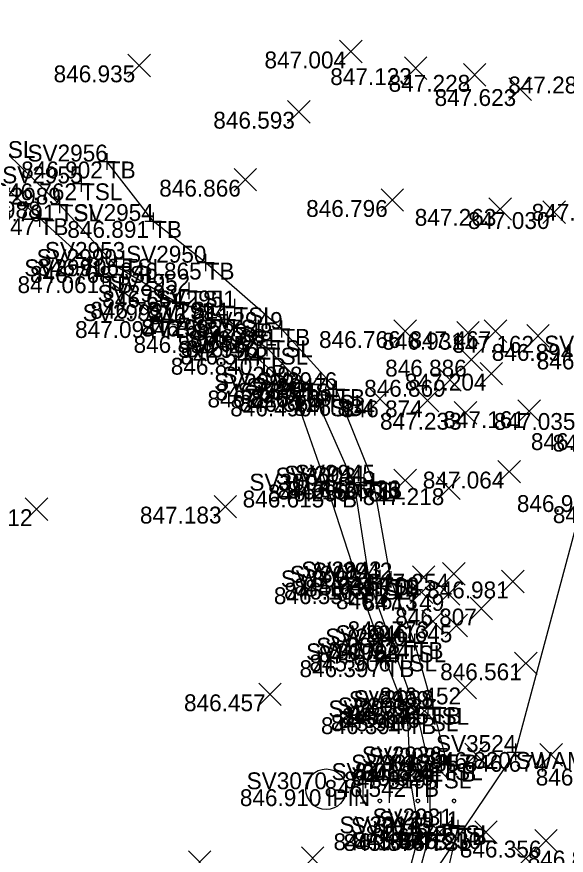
# Model space of a CAD drawing. Extents: x 2228183 to 2230895, y 679226 to 682223.
# Drawn here: x 2228252.61 to 2228285.17, y 680625.35 to 680675.06 of the extents above; entities that cross this region are included whole.
import ezdxf

# ---------------------------------------------------------------- set-up
doc = ezdxf.new("R2010")
doc.units = 0
for name, color, linetype in [('HY_X_Water_Edge', 7, 'Continuous'), ('RS_Raster1', 7, 'Continuous'), ('SC_Scratch1', 7, 'Continuous'), ('SV_P_Control_Cells_Set', 7, 'Continuous'), ('SV_X_Random_Point', 7, 'Continuous'), ('SV_X_Shot_Marker', 7, 'Continuous'), ('SV_X_Text_Comment', 7, 'Continuous'), ('SV_X_Toe_of_Slope', 7, 'Continuous'), ('SV_X_Top_of_Bank', 7, 'Continuous')]:
    doc.layers.add(name, color=color, linetype=linetype)

msp = doc.modelspace()

# ---------------------------------------------------------------- linework, layer by layer
at = {"layer": 'HY_X_Water_Edge'}
msp.add_lwpolyline([(2228257.254, 680599.372), (2228272.802, 680617.571), (2228282.168, 680631.469), (2228288.524, 680655.152), (2228295.689, 680691.668), (2228303.446, 680727.882), (2228301.785, 680777.477), (2228295.766, 680798.984)], dxfattribs=at)
at = {"layer": 'RS_Raster1'}
for points in [[(2228272.957, 680630.062), (2228273.31, 680630.062)], [(2228273.134, 680628.462), (2228273.134, 680630.062)], [(2228274.699, 680628.462), (2228274.699, 680630.062), (2228275.228, 680630.062), (2228275.283, 680630.049), (2228275.36, 680630.024), (2228275.394, 680629.999), (2228275.427, 680629.974), (2228275.471, 680629.911), (2228275.504, 680629.848), (2228275.526, 680629.747), (2228275.526, 680629.596), (2228275.515, 680629.545), (2228275.493, 680629.47), (2228275.449, 680629.382), (2228275.404, 680629.344), (2228275.371, 680629.319), (2228275.316, 680629.293), (2228275.228, 680629.281), (2228274.699, 680629.281)], [(2228277.708, 680630.062), (2228276.948, 680630.062), (2228276.948, 680628.462)], [(2228276.948, 680629.281), (2228277.488, 680629.281)], [(2228274.093, 680628.676), (2228274.148, 680628.676), (2228274.181, 680628.651), (2228274.214, 680628.601), (2228274.214, 680628.538), (2228274.181, 680628.487), (2228274.148, 680628.462), (2228274.093, 680628.462), (2228274.06, 680628.487), (2228274.027, 680628.538), (2228274.027, 680628.601), (2228274.06, 680628.651), (2228274.093, 680628.676)], [(2228276.342, 680628.676), (2228276.397, 680628.676), (2228276.43, 680628.651), (2228276.463, 680628.601), (2228276.463, 680628.538), (2228276.43, 680628.487), (2228276.397, 680628.462), (2228276.342, 680628.462), (2228276.308, 680628.487), (2228276.275, 680628.538), (2228276.275, 680628.601), (2228276.308, 680628.651), (2228276.342, 680628.676)], [(2228278.491, 680628.676), (2228278.546, 680628.676), (2228278.579, 680628.651), (2228278.612, 680628.601), (2228278.612, 680628.538), (2228278.579, 680628.487), (2228278.546, 680628.462), (2228278.491, 680628.462), (2228278.458, 680628.487), (2228278.425, 680628.538), (2228278.425, 680628.601), (2228278.458, 680628.651), (2228278.491, 680628.676)], [(2228272.957, 680628.462), (2228273.31, 680628.462)]]:
    msp.add_lwpolyline(points, dxfattribs=at)
msp.add_circle((2228270.943, 680629.262), 1.2, dxfattribs=at)
at = {"layer": 'SV_X_Random_Point'}
for p, q in [((2228271.742, 680672.332), (2228273.076, 680673.667)), ((2228271.742, 680673.667), (2228273.076, 680672.332)), ((2228259.198, 680671.507), (2228260.532, 680672.842)), ((2228259.198, 680672.842), (2228260.532, 680671.507)), ((2228275.583, 680671.343), (2228276.917, 680672.678)), ((2228275.583, 680672.678), (2228276.917, 680671.343)), ((2228279.077, 680670.946), (2228280.411, 680672.281)), ((2228279.077, 680672.281), (2228280.411, 680670.946)), ((2228281.765, 680670.103), (2228283.099, 680671.438)), ((2228281.765, 680671.438), (2228283.099, 680670.103)), ((2228268.653, 680668.759), (2228269.987, 680670.094)), ((2228268.653, 680670.094), (2228269.987, 680668.759)), ((2228265.49, 680664.729), (2228266.824, 680666.064)), ((2228265.49, 680666.064), (2228266.824, 680664.729)), ((2228274.194, 680663.525), (2228275.528, 680664.86)), ((2228274.194, 680664.86), (2228275.528, 680663.525)), ((2228280.588, 680662.998), (2228281.922, 680664.333)), ((2228280.588, 680664.333), (2228281.922, 680662.998)), ((2228283.788, 680662.81), (2228285.122, 680664.145)), ((2228283.788, 680664.145), (2228285.122, 680662.81)), ((2228274.958, 680655.756), (2228276.292, 680657.091)), ((2228274.958, 680657.091), (2228276.292, 680655.756)), ((2228280.313, 680655.747), (2228281.647, 680657.082)), ((2228280.313, 680657.082), (2228281.647, 680655.747)), ((2228278.679, 680655.654), (2228280.013, 680656.989)), ((2228278.679, 680656.989), (2228280.013, 680655.654)), ((2228282.829, 680655.472), (2228284.163, 680656.807)), ((2228282.829, 680656.807), (2228284.163, 680655.472)), ((2228278.875, 680654.059), (2228280.209, 680655.394)), ((2228278.875, 680655.394), (2228280.209, 680654.059)), ((2228280.059, 680653.231), (2228281.393, 680654.566)), ((2228280.059, 680654.566), (2228281.393, 680653.231)), ((2228277.61, 680652.867), (2228278.944, 680654.202)), ((2228277.61, 680654.202), (2228278.944, 680652.867)), ((2228273.463, 680651.736), (2228274.797, 680653.071)), ((2228273.463, 680653.071), (2228274.797, 680651.736)), ((2228276.284, 680651.646), (2228277.618, 680652.981)), ((2228276.284, 680652.981), (2228277.618, 680651.646)), ((2228278.532, 680650.913), (2228279.866, 680652.248)), ((2228278.532, 680652.248), (2228279.866, 680650.913)), ((2228282.298, 680651.009), (2228283.632, 680652.344)), ((2228282.298, 680652.344), (2228283.632, 680651.009)), ((2228281.121, 680647.425), (2228282.455, 680648.76)), ((2228281.121, 680648.76), (2228282.455, 680647.425)), ((2228274.957, 680646.904), (2228276.291, 680648.239)), ((2228274.957, 680648.239), (2228276.291, 680646.904)), ((2228277.542, 680646.444), (2228278.876, 680647.779)), ((2228277.542, 680647.779), (2228278.876, 680646.444)), ((2228264.306, 680645.347), (2228265.64, 680646.682)), ((2228264.306, 680646.682), (2228265.64, 680645.347)), ((2228253.114, 680645.195), (2228254.448, 680646.53)), ((2228253.114, 680646.53), (2228254.448, 680645.195)), ((2228277.839, 680641.366), (2228279.173, 680642.701)), ((2228277.839, 680642.701), (2228279.173, 680641.366)), ((2228276.049, 680641.163), (2228277.383, 680642.498)), ((2228276.049, 680642.498), (2228277.383, 680641.163)), ((2228281.34, 680640.911), (2228282.674, 680642.246)), ((2228281.34, 680642.246), (2228282.674, 680640.911)), ((2228275.925, 680640.267), (2228277.259, 680641.602)), ((2228275.925, 680641.602), (2228277.259, 680640.267)), ((2228277.523, 680640.173), (2228278.857, 680641.508)), ((2228277.523, 680641.508), (2228278.857, 680640.173)), ((2228279.465, 680639.305), (2228280.799, 680640.64)), ((2228279.465, 680640.64), (2228280.799, 680639.305)), ((2228276.609, 680638.549), (2228277.943, 680639.884)), ((2228276.609, 680639.884), (2228277.943, 680638.549)), ((2228277.985, 680638.305), (2228279.319, 680639.64)), ((2228277.985, 680639.64), (2228279.319, 680638.305)), ((2228282.111, 680636.056), (2228283.445, 680637.391)), ((2228282.111, 680637.391), (2228283.445, 680636.056)), ((2228278.507, 680634.626), (2228279.841, 680635.961)), ((2228278.507, 680635.961), (2228279.841, 680634.626)), ((2228266.95, 680634.221), (2228268.284, 680635.556)), ((2228266.95, 680635.556), (2228268.284, 680634.221)), ((2228276.099, 680633.231), (2228277.433, 680634.566)), ((2228276.099, 680634.566), (2228277.433, 680633.231)), ((2228279.16, 680630.658), (2228280.494, 680631.993)), ((2228279.16, 680631.993), (2228280.494, 680630.658)), ((2228283.606, 680630.632), (2228284.94, 680631.967)), ((2228283.606, 680631.967), (2228284.94, 680630.632)), ((2228276.908, 680629.804), (2228278.242, 680631.139)), ((2228276.908, 680631.139), (2228278.242, 680629.804)), ((2228277.001, 680626.06), (2228278.335, 680627.395)), ((2228277.001, 680627.395), (2228278.335, 680626.06)), ((2228279.743, 680626.05), (2228281.077, 680627.385)), ((2228279.743, 680627.385), (2228281.077, 680626.05)), ((2228283.299, 680625.548), (2228284.633, 680626.883)), ((2228283.299, 680626.883), (2228284.633, 680625.548)), ((2228269.48, 680624.51), (2228270.814, 680625.845)), ((2228269.48, 680625.845), (2228270.814, 680624.51)), ((2228282.109, 680624.495), (2228283.443, 680625.83)), ((2228282.109, 680625.83), (2228283.443, 680624.495)), ((2228262.781, 680624.267), (2228264.115, 680625.602)), ((2228262.781, 680625.602), (2228264.115, 680624.267))]:
    msp.add_line(p, q, dxfattribs=at)
at = {"layer": 'SV_X_Shot_Marker'}
for p, q in [((2228257.947, 680666.978), (2228257.947, 680665.978)), ((2228257.947, 680666.978), (2228257.947, 680665.978)), ((2228257.447, 680666.478), (2228258.447, 680666.478)), ((2228257.447, 680666.478), (2228258.447, 680666.478)), ((2228257.947, 680666.478), (2228257.947, 680666.478)), ((2228257.947, 680666.478), (2228257.947, 680666.478)), ((2228256.418, 680665.682), (2228256.418, 680664.682)), ((2228255.918, 680665.182), (2228256.918, 680665.182)), ((2228256.418, 680665.182), (2228256.418, 680665.182)), ((2228255.149, 680664.423), (2228255.149, 680663.423)), ((2228253.963, 680663.611), (2228253.963, 680662.611)), ((2228254.649, 680663.923), (2228255.649, 680663.923)), ((2228255.149, 680663.923), (2228255.149, 680663.923)), ((2228253.463, 680663.111), (2228254.463, 680663.111)), ((2228253.963, 680663.111), (2228253.963, 680663.111)), ((2228260.691, 680663.45), (2228260.691, 680662.45)), ((2228260.191, 680662.95), (2228261.191, 680662.95)), ((2228260.691, 680662.95), (2228260.691, 680662.95)), ((2228258.941, 680661.204), (2228258.941, 680660.204)), ((2228263.802, 680660.981), (2228263.802, 680659.981)), ((2228258.441, 680660.704), (2228259.441, 680660.704)), ((2228258.499, 680660.78), (2228258.499, 680659.78)), ((2228258.941, 680660.704), (2228258.941, 680660.704)), ((2228263.302, 680660.481), (2228264.302, 680660.481)), ((2228263.802, 680660.481), (2228263.802, 680660.481)), ((2228257.74, 680660.176), (2228257.74, 680659.176)), ((2228257.999, 680660.28), (2228258.999, 680660.28)), ((2228258.499, 680660.28), (2228258.499, 680660.28)), ((2228257.24, 680659.676), (2228258.24, 680659.676)), ((2228257.74, 680659.676), (2228257.74, 680659.676)), ((2228262.801, 680659.31), (2228262.801, 680658.31)), ((2228262.065, 680658.658), (2228262.065, 680657.658)), ((2228262.301, 680658.81), (2228263.301, 680658.81)), ((2228262.801, 680658.81), (2228262.801, 680658.81)), ((2228261.565, 680658.158), (2228262.565, 680658.158)), ((2228262.065, 680658.158), (2228262.065, 680658.158)), ((2228265.51, 680658.329), (2228265.51, 680657.329)), ((2228261.188, 680657.515), (2228261.188, 680656.515)), ((2228265.01, 680657.829), (2228266.01, 680657.829)), ((2228265.069, 680657.603), (2228265.069, 680656.603)), ((2228265.51, 680657.829), (2228265.51, 680657.829)), ((2228260.688, 680657.015), (2228261.688, 680657.015)), ((2228261.188, 680657.015), (2228261.188, 680657.015)), ((2228264.569, 680657.103), (2228265.569, 680657.103)), ((2228265.069, 680657.103), (2228265.069, 680657.103)), ((2228268.291, 680657.052), (2228268.291, 680656.052)), ((2228264.635, 680656.634), (2228264.635, 680655.634)), ((2228267.791, 680656.552), (2228268.791, 680656.552)), ((2228268.291, 680656.552), (2228268.291, 680656.552)), ((2228264.135, 680656.134), (2228265.135, 680656.134)), ((2228264.635, 680656.134), (2228264.635, 680656.134)), ((2228267.7, 680656.375), (2228267.7, 680655.375)), ((2228267.2, 680655.875), (2228268.2, 680655.875)), ((2228267.428, 680655.937), (2228267.428, 680654.937)), ((2228267.7, 680655.875), (2228267.7, 680655.875)), ((2228266.851, 680655.34), (2228266.851, 680654.34)), ((2228266.928, 680655.437), (2228267.928, 680655.437)), ((2228267.428, 680655.437), (2228267.428, 680655.437)), ((2228266.351, 680654.84), (2228267.351, 680654.84)), ((2228266.851, 680654.84), (2228266.851, 680654.84)), ((2228269.483, 680653.812), (2228269.483, 680652.812)), ((2228268.98, 680653.399), (2228268.98, 680652.399)), ((2228268.983, 680653.312), (2228269.983, 680653.312)), ((2228269.483, 680653.312), (2228269.483, 680653.312)), ((2228270.907, 680653.136), (2228270.907, 680652.136)), ((2228271.541, 680653.482), (2228271.541, 680652.482)), ((2228268.48, 680652.899), (2228269.48, 680652.899)), ((2228268.98, 680652.899), (2228268.98, 680652.899)), ((2228270.371, 680652.868), (2228270.371, 680651.868)), ((2228270.407, 680652.636), (2228271.407, 680652.636)), ((2228270.907, 680652.636), (2228270.907, 680652.636)), ((2228271.041, 680652.982), (2228272.041, 680652.982)), ((2228271.541, 680652.982), (2228271.541, 680652.982)), ((2228269.871, 680652.368), (2228270.871, 680652.368)), ((2228270.371, 680652.368), (2228270.371, 680652.368)), ((2228272.604, 680647.828), (2228272.604, 680646.828)), ((2228273.181, 680647.94), (2228273.181, 680646.94)), ((2228273.746, 680647.995), (2228273.746, 680646.995)), ((2228271.065, 680647.466), (2228271.065, 680646.466)), ((2228272.104, 680647.328), (2228273.104, 680647.328)), ((2228272.604, 680647.328), (2228272.604, 680647.328)), ((2228272.681, 680647.44), (2228273.681, 680647.44)), ((2228273.181, 680647.44), (2228273.181, 680647.44)), ((2228273.246, 680647.495), (2228274.246, 680647.495)), ((2228273.746, 680647.495), (2228273.746, 680647.495)), ((2228270.565, 680646.966), (2228271.565, 680646.966)), ((2228271.065, 680646.966), (2228271.065, 680646.966)), ((2228274.131, 680642.26), (2228274.131, 680641.26)), ((2228274.779, 680642.193), (2228274.779, 680641.193)), ((2228272.926, 680641.737), (2228272.926, 680640.737)), ((2228273.515, 680642.005), (2228273.515, 680641.005)), ((2228273.631, 680641.76), (2228274.631, 680641.76)), ((2228274.131, 680641.76), (2228274.131, 680641.76)), ((2228274.279, 680641.693), (2228275.279, 680641.693)), ((2228274.779, 680641.693), (2228274.779, 680641.693)), ((2228272.426, 680641.237), (2228273.426, 680641.237)), ((2228272.926, 680641.237), (2228272.926, 680641.237)), ((2228273.015, 680641.505), (2228274.015, 680641.505)), ((2228273.515, 680641.505), (2228273.515, 680641.505)), ((2228275.604, 680638.287), (2228275.604, 680637.287)), ((2228276.183, 680638.482), (2228276.183, 680637.482)), ((2228275.054, 680637.746), (2228275.054, 680636.746)), ((2228275.104, 680637.787), (2228276.104, 680637.787)), ((2228275.604, 680637.787), (2228275.604, 680637.787)), ((2228275.683, 680637.982), (2228276.683, 680637.982)), ((2228276.183, 680637.982), (2228276.183, 680637.982)), ((2228274.458, 680637.41), (2228274.458, 680636.41)), ((2228274.554, 680637.246), (2228275.554, 680637.246)), ((2228275.054, 680637.246), (2228275.054, 680637.246)), ((2228273.958, 680636.91), (2228274.958, 680636.91)), ((2228274.458, 680636.91), (2228274.458, 680636.91)), ((2228276.326, 680634.2), (2228276.326, 680633.2)), ((2228276.964, 680634.582), (2228276.964, 680633.582)), ((2228277.264, 680634.63), (2228277.264, 680633.63)), ((2228275.756, 680634.029), (2228275.756, 680633.029)), ((2228275.826, 680633.7), (2228276.826, 680633.7)), ((2228276.326, 680633.7), (2228276.326, 680633.7)), ((2228276.464, 680634.082), (2228277.464, 680634.082)), ((2228276.764, 680634.13), (2228277.764, 680634.13)), ((2228276.964, 680634.082), (2228276.964, 680634.082)), ((2228277.264, 680634.13), (2228277.264, 680634.13)), ((2228275.256, 680633.529), (2228276.256, 680633.529)), ((2228275.756, 680633.529), (2228275.756, 680633.529)), ((2228282.168, 680631.969), (2228282.168, 680630.969)), ((2228277.76, 680631.297), (2228277.76, 680630.297)), ((2228278.132, 680631.216), (2228278.132, 680630.216)), ((2228281.668, 680631.469), (2228282.668, 680631.469)), ((2228282.168, 680631.469), (2228282.168, 680631.469)), ((2228277.096, 680630.812), (2228277.096, 680629.812)), ((2228277.26, 680630.797), (2228278.26, 680630.797)), ((2228277.632, 680630.716), (2228278.632, 680630.716)), ((2228277.76, 680630.797), (2228277.76, 680630.797)), ((2228278.132, 680630.716), (2228278.132, 680630.716)), ((2228275.923, 680630.309), (2228275.923, 680629.309)), ((2228276.596, 680630.312), (2228277.596, 680630.312)), ((2228277.096, 680630.312), (2228277.096, 680630.312)), ((2228275.423, 680629.809), (2228276.423, 680629.809)), ((2228275.923, 680629.809), (2228275.923, 680629.809)), ((2228278.367, 680627.619), (2228278.367, 680626.619)), ((2228278.75, 680627.457), (2228278.75, 680626.457)), ((2228276.449, 680627.147), (2228276.449, 680626.147)), ((2228277.073, 680627.106), (2228277.073, 680626.106)), ((2228277.867, 680627.119), (2228278.867, 680627.119)), ((2228278.25, 680626.957), (2228279.25, 680626.957)), ((2228278.367, 680627.119), (2228278.367, 680627.119)), ((2228278.75, 680626.957), (2228278.75, 680626.957)), ((2228275.949, 680626.647), (2228276.949, 680626.647)), ((2228276.449, 680626.647), (2228276.449, 680626.647)), ((2228276.573, 680626.606), (2228277.573, 680626.606)), ((2228277.073, 680626.606), (2228277.073, 680626.606))]:
    msp.add_line(p, q, dxfattribs=at)
at = {"layer": 'SV_X_Toe_of_Slope'}
msp.add_lwpolyline([(2228251.267, 680667.687), (2228255.149, 680663.923), (2228258.499, 680660.28), (2228262.065, 680658.158), (2228265.069, 680657.103), (2228267.428, 680655.437), (2228269.483, 680653.312), (2228270.371, 680652.368), (2228272.604, 680647.328), (2228273.515, 680641.505), (2228275.054, 680637.246), (2228276.326, 680633.7), (2228277.096, 680630.312), (2228277.073, 680626.606), (2228276.119, 680623.113)], dxfattribs=at)
at = {"layer": 'SV_X_Top_of_Bank'}
for points in [[(2228278.132, 680630.716), (2228277.264, 680634.13), (2228276.183, 680637.982), (2228274.779, 680641.693), (2228273.746, 680647.495), (2228271.541, 680652.982), (2228268.291, 680656.552), (2228263.802, 680660.481), (2228260.691, 680662.95), (2228257.947, 680666.478)], [(2228250.294, 680666.425), (2228253.963, 680663.111), (2228257.74, 680659.676), (2228261.188, 680657.015), (2228264.635, 680656.134), (2228266.851, 680654.84), (2228268.98, 680652.899), (2228271.065, 680646.966), (2228272.926, 680641.237), (2228274.458, 680636.91), (2228275.756, 680633.529), (2228275.923, 680629.809), (2228276.449, 680626.647), (2228275.536, 680623.225), (2228275.317, 680622.149), (2228274.643, 680621.896), (2228273.31, 680622.82), (2228272.512, 680623.797)], [(2228285.062, 680599.425), (2228282.886, 680598.842), (2228280.492, 680599.37), (2228279.968, 680599.959), (2228279.013, 680602.252), (2228278.966, 680603.397), (2228280.378, 680604.093), (2228281.452, 680605.233), (2228281.475, 680607.501), (2228280.954, 680609.441), (2228279.558, 680612.949), (2228279.046, 680613.794), (2228277.746, 680617.324), (2228277.262, 680619.298), (2228277.784, 680622.75), (2228278.75, 680626.957)]]:
    msp.add_lwpolyline(points, dxfattribs=at)

# ---------------------------------------------------------------- texts
at = {"layer": 'SC_Scratch1'}
for s, p in [('847.004', (2228267.287, 680671.999)), ('846.935', (2228254.795, 680671.174)), ('847.123', (2228271.186, 680671.01)), ('847.228', (2228274.644, 680670.613)), ('847.280', (2228281.728, 680670.514)), ('847.623', (2228277.368, 680669.77)), ('846.593', (2228264.256, 680668.426)), ('846.902', (2228252.874, 680665.478)), ('846.762', (2228251.345, 680664.182)), ('846.866', (2228261.053, 680664.396)), ('846.796', (2228269.757, 680663.192)), ('847.056', (2228283.118, 680662.965)), ('846.791', (2228250.067, 680662.923)), ('847.263', (2228276.191, 680662.665)), ('847.030', (2228279.341, 680662.477)), ('847.047', (2228248.867, 680662.111)), ('846.891', (2228255.609, 680661.95)), ('846.706', (2228253.837, 680659.704)), ('846.865', (2228258.732, 680659.481)), ('846.768', (2228253.399, 680659.28)), ('847.061', (2228252.658, 680658.676)), ('846.664', (2228257.679, 680657.81)), ('846.707', (2228256.969, 680657.158)), ('846.611', (2228260.428, 680656.829)), ('847.094', (2228256.066, 680656.015)), ('846.652', (2228259.996, 680656.103)), ('846.681', (2228263.209, 680655.552)), ('846.896', (2228259.531, 680655.134)), ('846.766', (2228270.521, 680655.423)), ('846.931', (2228274.264, 680655.321)), ('847.467', (2228275.884, 680655.414)), ('847.162', (2228278.423, 680655.139)), ('846.475', (2228262.63, 680654.875)), ('846.894', (2228280.754, 680654.658)), ('846.544', (2228262.306, 680654.437)), ('846.976', (2228283.42, 680654.152)), ('846.840', (2228261.737, 680653.84)), ('846.886', (2228274.438, 680653.726)), ('846.869', (2228273.193, 680652.534)), ('847.204', (2228275.604, 680652.898)), ('846.556', (2228264.379, 680652.312)), ('846.825', (2228263.91, 680651.899)), ('846.350', (2228265.793, 680651.636)), ('846.609', (2228266.457, 680651.982)), ('846.490', (2228265.257, 680651.368)), ('846.834', (2228269.008, 680651.403)), ('846.874', (2228271.829, 680651.313)), ('847.233', (2228274.135, 680650.58)), ('847.161', (2228277.883, 680650.676)), ('847.035', (2228280.877, 680650.565)), ('846.982', (2228283.072, 680649.371)), ('846.906', (2228284.354, 680649.28)), ('847.064', (2228276.666, 680647.092)), ('846.736', (2228270.52, 680646.571)), ('846.290', (2228267.49, 680646.328)), ('846.150', (2228268.067, 680646.44)), ('846.526', (2228268.642, 680646.495)), ('847.218', (2228273.109, 680646.111)), ('846.615', (2228265.995, 680645.966)), ('846.909', (2228282.24, 680645.699)), ('847.212', (2228248.708, 680644.862)), ('847.183', (2228259.909, 680645.014)), ('846.865', (2228284.369, 680645.038)), ('845.931', (2228269.049, 680640.76)), ('846.611', (2228269.697, 680640.693)), ('846.709', (2228271.632, 680640.83)), ('847.254', (2228273.384, 680641.033)), ('846.981', (2228276.925, 680640.578)), ('846.551', (2228267.844, 680640.237)), ('846.103', (2228268.451, 680640.505)), ('846.613', (2228271.528, 680639.934)), ('847.149', (2228273.106, 680639.84)), ('846.807', (2228275.036, 680638.972)), ('846.773', (2228272.212, 680638.216)), ('846.645', (2228273.582, 680637.972)), ('845.788', (2228270.504, 680636.787)), ('846.224', (2228271.061, 680636.982)), ('845.906', (2228269.95, 680636.246)), ('846.397', (2228269.362, 680635.91)), ('846.561', (2228277.696, 680635.723)), ('846.452', (2228274.101, 680634.293)), ('846.457', (2228262.521, 680633.888)), ('846.365', (2228272.194, 680633.13)), ('845.916', (2228271.222, 680632.7)), ('845.846', (2228271.662, 680632.898)), ('845.671', (2228271.882, 680633.082)), ('846.394', (2228270.634, 680632.529)), ('846.357', (2228274.731, 680630.325)), ('846.820', (2228277.054, 680630.469)), ('846.674', (2228279.151, 680630.299)), ('845.834', (2228272.638, 680629.797)), ('846.241', (2228273.05, 680629.716)), ('845.919', (2228272.012, 680629.312)), ('845.829', (2228272.491, 680629.471)), ('846.965', (2228283.359, 680629.48)), ('846.542', (2228270.85, 680628.809)), ('846.910', (2228265.829, 680628.262)), ('845.857', (2228272.572, 680625.727)), ('845.979', (2228273.283, 680626.119)), ('846.248', (2228273.65, 680625.957)), ('846.230', (2228275.296, 680625.717)), ('846.105', (2228271.379, 680625.647)), ('845.876', (2228271.969, 680625.606)), ('846.356', (2228278.862, 680625.215)), ('846.843', (2228282.882, 680624.625))]:
    msp.add_text(s, height=1, dxfattribs=at).set_placement(p)
at = {"layer": 'SV_P_Control_Cells_Set'}
for s, p in [('SV2956', (2228253.245, 680666.478)), ('SV2955', (2228251.749, 680665.182)), ('SV2989', (2228250.467, 680663.923)), ('SV2988', (2228249.264, 680663.111)), ('SV2954', (2228255.971, 680662.95)), ('SV2953', (2228254.279, 680660.704)), ('SV2950', (2228259.09, 680660.481)), ('SV2990', (2228253.787, 680660.28)), ('SV2991', (2228253.06, 680659.676)), ('SV2952', (2228258.13, 680658.81)), ('SV2993', (2228257.403, 680658.158)), ('SV2951', (2228260.83, 680657.829)), ('SV2992', (2228256.517, 680657.015)), ('SV2994', (2228260.349, 680657.103)), ('SV2949', (2228263.609, 680656.552)), ('SV2995', (2228259.966, 680656.134)), ('SV2948', (2228263.001, 680655.875)), ('SV2997', (2228262.734, 680655.437)), ('SV3525', (2228283.855, 680655.152)), ('SV2996', (2228262.149, 680654.84)), ('SV2998', (2228264.784, 680653.312)), ('SV2999', (2228264.298, 680652.899)), ('SV2947', (2228266.213, 680652.636)), ('SV2946', (2228266.839, 680652.982)), ('SV3001', (2228265.691, 680652.368)), ('SV3003', (2228267.942, 680647.328)), ('SV2944', (2228268.461, 680647.44)), ('SV2945', (2228269.077, 680647.495)), ('SV3002', (2228266.394, 680646.966)), ('SV2943', (2228269.469, 680641.76)), ('SV2942', (2228270.108, 680641.693)), ('SV3005', (2228268.257, 680641.237)), ('SV3004', (2228268.795, 680641.505)), ('SV2940', (2228270.892, 680637.787)), ('SV2941', (2228271.503, 680637.982)), ('SV3007', (2228270.36, 680637.246)), ('SV3006', (2228269.756, 680636.91)), ('SV2938', (2228272.565, 680634.13)), ('SV3008', (2228271.627, 680633.7)), ('SV2939', (2228272.282, 680634.082)), ('SV3009', (2228271.074, 680633.529)), ('SV3524', (2228277.448, 680631.469)), ('SV2936', (2228273.058, 680630.797)), ('SV2935', (2228273.463, 680630.716)), ('SV3012', (2228272.425, 680630.312)), ('SV3013', (2228271.261, 680629.809)), ('SV3070', (2228266.231, 680629.262)), ('SV2931', (2228273.687, 680627.119)), ('SV2911', (2228274.07, 680626.957)), ('SV3014', (2228271.729, 680626.647)), ('SV3015', (2228272.404, 680626.606))]:
    msp.add_text(s, height=1, dxfattribs=at).set_placement(p)
at = {"layer": 'SV_X_Text_Comment'}
for s, p in [('TSL', (2228251.267, 680666.687)), ('TB', (2228257.947, 680665.478)), ('TSL', (2228256.418, 680664.182)), ('TSL', (2228255.149, 680662.923)), ('TB', (2228253.963, 680662.111)), ('TB', (2228260.691, 680661.95)), ('TSL', (2228258.941, 680659.704)), ('TB', (2228263.802, 680659.481)), ('TSL', (2228258.499, 680659.28)), ('TB', (2228257.74, 680658.676)), ('TSL', (2228262.801, 680657.81)), ('TSL', (2228262.065, 680657.158)), ('TSL', (2228265.51, 680656.829)), ('TB', (2228261.188, 680656.015)), ('TSL', (2228265.069, 680656.103)), ('TB', (2228268.291, 680655.552)), ('TB', (2228264.635, 680655.134)), ('TSL', (2228267.7, 680654.875)), ('TSL', (2228267.428, 680654.437)), ('TB', (2228266.851, 680653.84)), ('TSL', (2228269.483, 680652.312)), ('TB', (2228268.98, 680651.899)), ('TSL', (2228270.907, 680651.636)), ('TB', (2228271.541, 680651.982)), ('TSL', (2228270.371, 680651.368)), ('TSL', (2228272.604, 680646.328)), ('TSL', (2228273.181, 680646.44)), ('TB', (2228273.746, 680646.495)), ('TB', (2228271.065, 680645.966)), ('TSL', (2228274.131, 680640.76)), ('TB', (2228274.779, 680640.693)), ('TB', (2228272.926, 680640.237)), ('TSL', (2228273.515, 680640.505)), ('TSL', (2228275.604, 680636.787)), ('TB', (2228276.183, 680636.982)), ('TSL', (2228275.054, 680636.246)), ('TB', (2228274.458, 680635.91)), ('TSL', (2228276.326, 680632.7)), ('TSL', (2228276.964, 680633.082)), ('TB', (2228277.264, 680633.13)), ('TB', (2228275.756, 680632.529)), ('SWAMP', (2228282.168, 680630.469)), ('TSL', (2228277.76, 680629.797)), ('TB', (2228278.132, 680629.716)), ('TSL', (2228277.096, 680629.312)), ('TB', (2228275.923, 680628.809)), ('IPIN', (2228270.943, 680628.262)), ('TSL', (2228278.367, 680626.119)), ('TB', (2228278.75, 680625.957)), ('TB', (2228276.449, 680625.647)), ('TSL', (2228277.073, 680625.606))]:
    msp.add_text(s, height=1, dxfattribs=at).set_placement(p)

doc.saveas('drawing.dxf')
